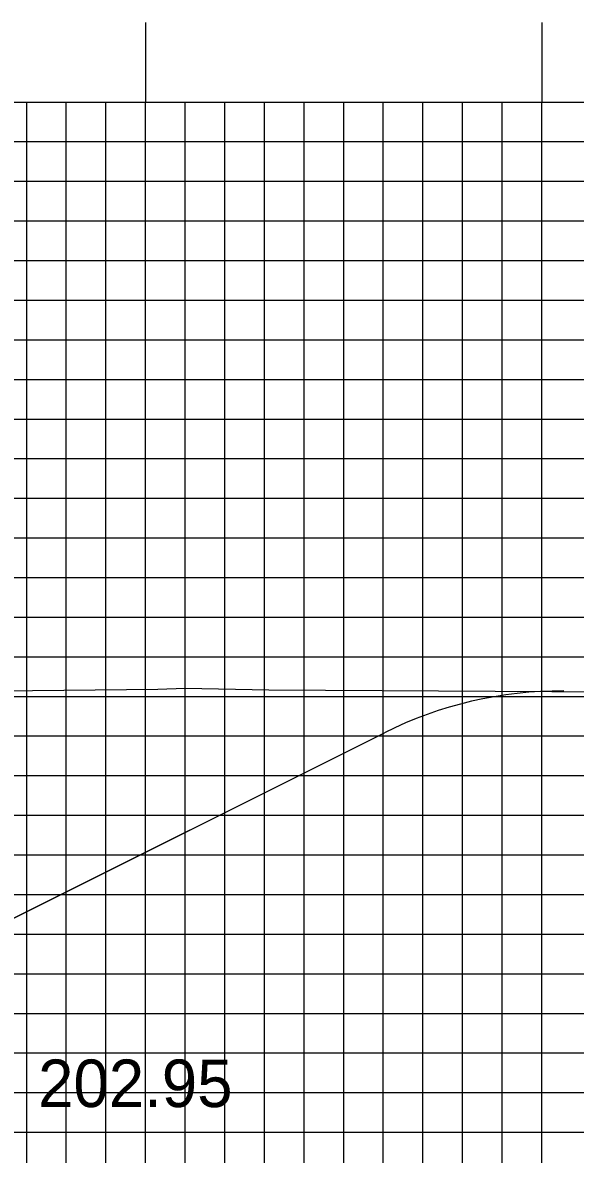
# Model space of a CAD drawing. Extents: x 852922 to 853266, y 364785 to 365005.
# Drawn here: x 853135.14 to 853149.09, y 364866.67 to 364895.24 of the extents above; entities that cross this region are included whole.
import ezdxf

# ---------------------------------------------------------------- set-up
doc = ezdxf.new("R2010")
doc.units = 0
for name, color, linetype in [('D_Drainage_Text', 7, 'Continuous'), ('D_Roadway_FinishedGrade', 7, 'Continuous'), ('D_Text_Standard', 7, 'Continuous'), ('MAJOR', 7, 'Continuous'), ('MINOR', 7, 'Continuous'), ('S_Roadway_Centerline', 7, 'Continuous')]:
    doc.layers.add(name, color=color, linetype=linetype)

msp = doc.modelspace()

# ---------------------------------------------------------------- linework, layer by layer
at = {"layer": 'D_Drainage_Text'}
msp.add_lwpolyline([(853132.039, 364871.199), (853134.039, 364872.199), (853144.271, 364877.315)], dxfattribs=at)
at = {"layer": 'D_Roadway_FinishedGrade'}
msp.add_line((853132.039, 364871.199), (853144.271, 364877.315), dxfattribs=at)
msp.add_arc((853148.743, 364868.37), 10, 89.6863, 116.5651, dxfattribs=at)
at = {"layer": 'MAJOR'}
for p, q in [((853138.244, 364895.237), (853138.244, 364893.233)), ((853148.244, 364895.237), (853148.244, 364893.233)), ((852948.244, 364893.233), (853228.244, 364893.233)), ((852948.244, 364893.233), (853228.244, 364893.233)), ((853138.244, 364858.233), (853138.244, 364893.233)), ((853148.244, 364858.233), (853148.244, 364893.233)), ((852948.244, 364888.233), (853228.244, 364888.233)), ((852948.244, 364883.233), (853228.244, 364883.233)), ((852948.244, 364878.233), (853228.244, 364878.233)), ((852948.244, 364873.233), (853228.244, 364873.233)), ((852948.244, 364868.233), (853228.244, 364868.233))]:
    msp.add_line(p, q, dxfattribs=at)
at = {"layer": 'MINOR'}
for p, q in [((853135.244, 364858.233), (853135.244, 364893.233)), ((853136.244, 364858.233), (853136.244, 364893.233)), ((853137.244, 364858.233), (853137.244, 364893.233)), ((853139.244, 364858.233), (853139.244, 364893.233)), ((853140.244, 364858.233), (853140.244, 364893.233)), ((853141.244, 364858.233), (853141.244, 364893.233)), ((853142.244, 364858.233), (853142.244, 364893.233)), ((853143.244, 364858.233), (853143.244, 364893.233)), ((853144.244, 364858.233), (853144.244, 364893.233)), ((853145.244, 364858.233), (853145.244, 364893.233)), ((853146.244, 364858.233), (853146.244, 364893.233)), ((853147.244, 364858.233), (853147.244, 364893.233)), ((852948.244, 364892.233), (853228.244, 364892.233)), ((852948.244, 364891.233), (853228.244, 364891.233)), ((852948.244, 364890.233), (853228.244, 364890.233)), ((852948.244, 364889.233), (853228.244, 364889.233)), ((852948.244, 364887.233), (853228.244, 364887.233)), ((852948.244, 364886.233), (853228.244, 364886.233)), ((852948.244, 364885.233), (853228.244, 364885.233)), ((852948.244, 364884.233), (853228.244, 364884.233)), ((852948.244, 364882.233), (853228.244, 364882.233)), ((852948.244, 364881.233), (853228.244, 364881.233)), ((852948.244, 364880.233), (853228.244, 364880.233)), ((852948.244, 364879.233), (853228.244, 364879.233)), ((852948.244, 364877.233), (853228.244, 364877.233)), ((852948.244, 364876.233), (853228.244, 364876.233)), ((852948.244, 364875.233), (853228.244, 364875.233)), ((852948.244, 364874.233), (853228.244, 364874.233)), ((852948.244, 364872.233), (853228.244, 364872.233)), ((852948.244, 364871.233), (853228.244, 364871.233)), ((852948.244, 364870.233), (853228.244, 364870.233)), ((852948.244, 364869.233), (853228.244, 364869.233)), ((852948.244, 364867.233), (853228.244, 364867.233))]:
    msp.add_line(p, q, dxfattribs=at)
at = {"layer": 'S_Roadway_Centerline'}
msp.add_lwpolyline([(852948.244, 364867.115), (852952.293, 364867.224), (852982.811, 364869.572), (852983.433, 364869.613), (852984.764, 364869.671), (852995.961, 364869.609), (853002.177, 364870.032), (853019.783, 364870.025), (853022.004, 364870.134), (853031.206, 364870.205), (853040.954, 364870.271), (853047.088, 364870.613), (853061.473, 364871.309), (853080.196, 364872.293), (853086.656, 364872.726), (853095.621, 364874.314), (853108.715, 364876.755), (853119.923, 364878.669), (853126.685, 364878.29), (853138.551, 364878.414), (853139.241, 364878.439), (853141.359, 364878.394), (853158.491, 364878.3)], dxfattribs=at)

# ---------------------------------------------------------------- texts
at = {"layer": 'D_Text_Standard'}
msp.add_text('202.95', height=1.2, dxfattribs=at).set_placement((853135.531, 364867.867))

doc.saveas('drawing.dxf')
